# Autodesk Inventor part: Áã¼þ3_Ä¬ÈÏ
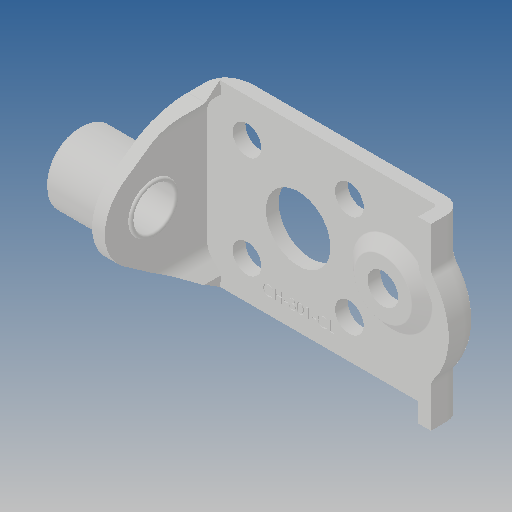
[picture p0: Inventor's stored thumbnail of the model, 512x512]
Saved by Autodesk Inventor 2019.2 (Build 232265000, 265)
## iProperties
Created: 2012-09
Part Number: Áã¼þ3_Ä¬ÈÏ
Material: Ogólny
Document SubType Name: Modeling
Designer: CADENGINEERING4
Density: 1 g/cm^3
Appearance: Domyślna
Author: CADENGINEERING4
Revision Number: ÈÎºÎ
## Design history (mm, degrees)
feature "ÇÐ³ý-À­Éì4"
node "Bryła1"
